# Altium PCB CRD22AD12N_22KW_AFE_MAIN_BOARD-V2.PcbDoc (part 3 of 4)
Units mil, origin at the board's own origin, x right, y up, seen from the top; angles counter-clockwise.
Board outline 14411 x 7330.3 mil, 4 copper layers (TOP, GND02, POWER03, BOTTOM), stack 78.531 mil thick; 589 components, 281 nets, 1401 pads, 282 vias.
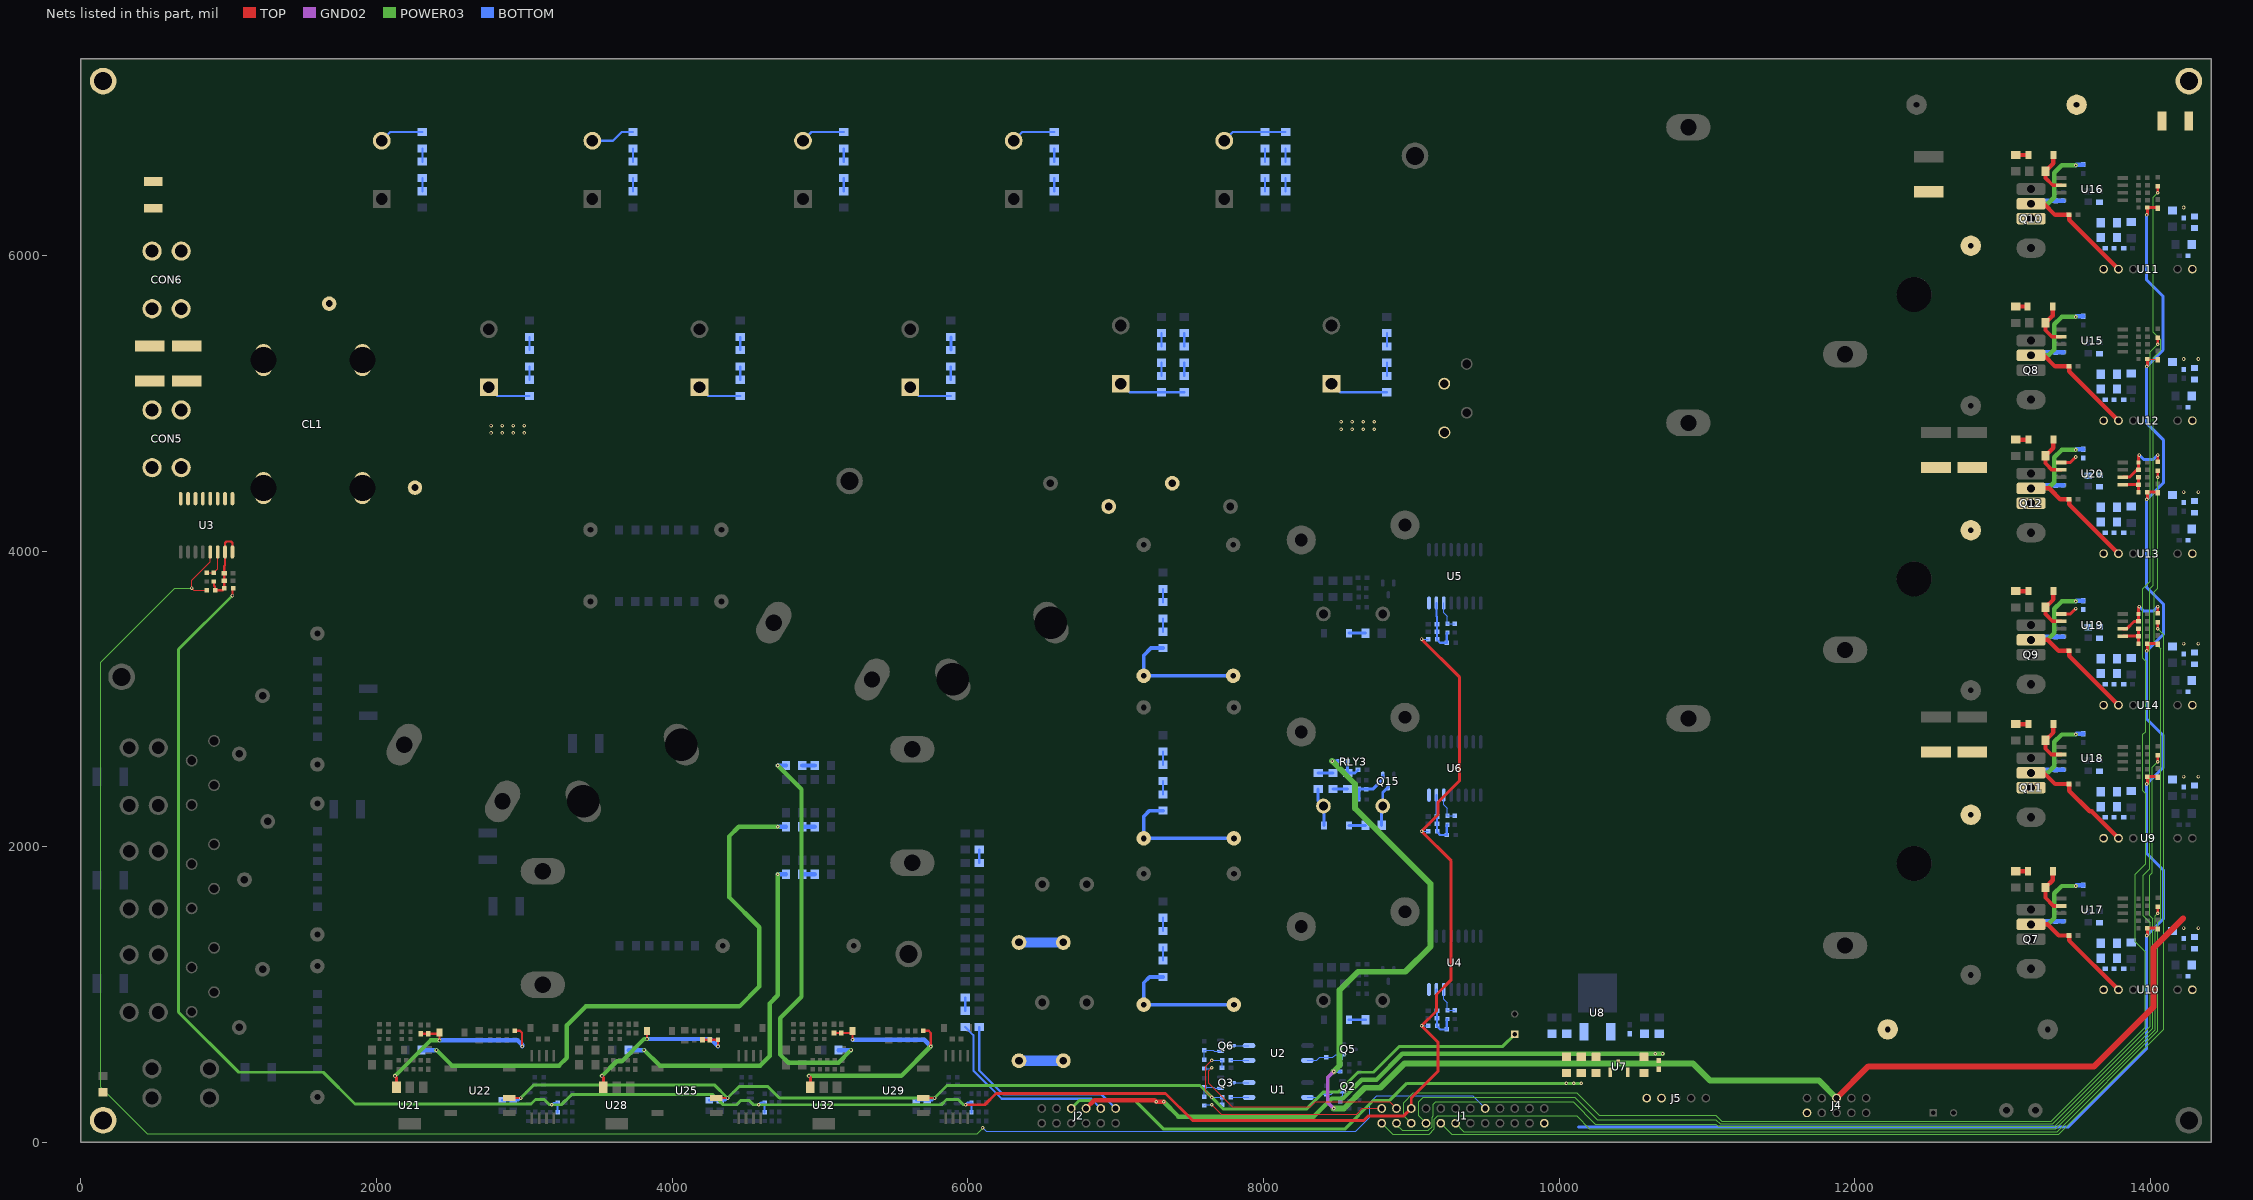
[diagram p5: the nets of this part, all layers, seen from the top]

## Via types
v1: diameter 24/24/24/24 (per signal layer), hole 12, TOP to BOTTOM, tented both sides, 282 vias

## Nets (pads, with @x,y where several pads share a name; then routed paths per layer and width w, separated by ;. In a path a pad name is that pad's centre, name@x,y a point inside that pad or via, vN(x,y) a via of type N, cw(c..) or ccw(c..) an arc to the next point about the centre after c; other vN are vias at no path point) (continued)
N17925295: C140.1 C141.1 R133.2 U19.1 | length 206.1
  TOP w20: U19.1@13814,3425 C141.1@13920.08,3425 ; R133.2@13920.08,3375 C141.1@13920.08,3425 ; C140.1@13920.08,3475 C141.1@13920.08,3425
N17925329: C142.1 R134.2 R136.1 U19.2 | length 423.8
  TOP w20: U19.2@13814,3475 13840,3475 13890,3525 C142.1@13920.08,3525 R136.1@13920.08,3575 13920.08,3620.08 v1(13925,3625) ; R134.2@14050,3579.92 v1(14050,3625)
  BOTTOM w20: v1(13925,3625) 13955,3595 14020,3595 v1(14050,3625)
N17925397: C143.1 C144.1 R135.1 U19.5 | length 114
  TOP w20: U19.5@13396.68,3575 13458.34,3575 v1(13495.34,3612)
N17925494: C147.1 C148.1 R137.2 U20.1 | length 206.1
  TOP w20: U20.1@13814,4450 C148.1@13920.08,4450 ; R137.2@13920.08,4400 C148.1@13920.08,4450 ; C147.1@13920.08,4500 C148.1@13920.08,4450
N17925544: C149.1 R138.2 R139.1 U20.2 | length 423.8
  TOP w20: U20.2@13814,4500 13816.5,4502.5 13861.3,4502.5 13903.29,4544.5 13914.58,4544.5 C149.1@13920.08,4550 R139.1@13920.08,4600 13920.08,4645.08 v1(13925,4650) ; R138.2@14050,4604.92 v1(14050,4650)
  BOTTOM w20: v1(13925,4650) 13955,4620 14020,4620 v1(14050,4650)
N17925612: C150.1 C151.1 R140.1 U20.5 | length 114
  TOP w20: U20.5@13396.68,4600 13458.34,4600 v1(13495.34,4637)
N17927817: C68.1 C69.1 R112.1 U10.1
N17928860: C86.1 C87.1 R114.1 U12.1
N17929090: C78.1 C79.1 R113.1 U11.1
N17930170: C104.1 C105.1 R116.1 U14.1
N17930400: C96.1 C97.1 R115.1 U13.1
N17951662: C39.1 C40.1 R98.2 R99.1 R100.1 U4.15 U4.16 | length 397.3
  BOTTOM w15: U4.15@9170,1034.76 9170,894.92 C40.1@9174.92,890 C39.1@9174.92,840 R98.2@9174.92,790 9174.92,785.08 9195,765 R100.1@9240.08,765 9240.08,830.16 R99.1@9245,835.08
N17951990: R99.2 R102.1 U4.14 | length 200.2
  BOTTOM w6: U4.14@9220,1034.76 9220,970 9245,945 R99.2@9245,894.92 R102.1@9295,894.92
N17952680: C41.1 C42.1 R103.2 R104.1 R105.1 U5.15 U5.16 | length 397.3
  BOTTOM w15: U5.15@9170,3649.76 9170,3560 9174.92,3555.08 C42.1@9174.92,3505 C41.1@9174.92,3455 R103.2@9174.92,3405 9174.92,3400.08 9195,3380 R105.1@9240.08,3380 9240.08,3445.16 R104.1@9245,3450.08
N17952780: R104.2 R109.1 U5.14 | length 200.2
  BOTTOM w6: U5.14@9220,3649.76 9220,3585 9245,3560 R104.2@9245,3509.92 R109.1@9295,3509.92
N17953229: C43.1 C44.1 R106.2 R107.1 R108.1 U6.15 U6.16 | length 397.3
  BOTTOM w15: U6.15@9170,2349.76 9170,2209.92 C44.1@9174.92,2205 C43.1@9174.92,2155 R106.2@9174.92,2105 9174.92,2100.08 9195,2080 R108.1@9240.08,2080 9240.08,2145.16 R107.1@9245,2150.08
N17953329: R107.2 R110.1 U6.14 | length 200.2
  BOTTOM w6: U6.14@9220,2349.76 9220,2285 9245,2260 R107.2@9245,2209.92 R110.1@9295,2209.92
N17988040: Q6.1 R67.1 R68.2 | length 178.5
  BOTTOM w6: R67.1@7600,559.92 R68.2@7600,625.08 7659.92,625.08 7667.4,617.6 Q6.1@7710.24,617.6
N17988101: Q6.3 U2.2 | length 112.4
  BOTTOM w6: Q6.3@7789.76,655 U2.2@7902.17,655
N17988123: Q5.1 R64.1 R66.2 U2.4 | length 321.9
  BOTTOM w6: U2.4@8297.83,555 8360,555 8380.08,575.08 R66.2@8425,575.08 8470.08,575.08 8487.6,592.6 Q5.1@8535.24,592.6 8535.24,565.24 8520.08,550.08 R64.1@8520.08,530
N17988189: R65.1 U2.1 | length 122.2
  BOTTOM w6: R65.1@7779.92,555 U2.1@7902.17,555
N17989219: Q3.1 R58.1 R59.2 | length 178.5
  BOTTOM w6: R58.1@7600,309.92 R59.2@7600,375.08 7662.52,375.08 7670,367.6 Q3.1@7710.24,367.6
N17989262: Q3.3 U1.2 | length 112.4
  BOTTOM w6: Q3.3@7789.76,405 U1.2@7902.17,405
N17989280: Q2.1 R51.1 R53.2 U1.4 | length 321.9
  BOTTOM w6: U1.4@8297.83,305 8365,305 8385.08,325.08 R53.2@8425,325.08 8460.08,325.08 8477.6,342.6 Q2.1@8535.24,342.6 8535.24,320.24 8520.08,305.08 R51.1@8520.08,280
N17989337: R52.1 U1.1 | length 122.2
  BOTTOM w6: R52.1@7779.92,305 U1.1@7902.17,305
N17992674: R73.1 R77.2 | length 89.8
  BOTTOM w15: R77.2@6077.76,1890.87 R73.1@6077.76,1980.63
N17992702: R92.1 R94.2 | length 89.8
  BOTTOM w15: R94.2@5982.76,890.87 R92.1@5982.76,980.63
N18031698: CL1.4 U3.1 U3.2 U3.3 U3.4
N18031715: C204.1 C205.1 CON5.1 CON5.2 CON5.3 CON5.4 U3.5 U3.6 U3.7 U3.8
N18031729: C37.1 C38.1 R95.2 R96.1 R97.1 U3.15 U3.16 | length 559.1
  TOP w15: R96.1@900,3795.08 900,3768 907.82,3760.18 907.82,3737.1 R97.1@909.92,3735 960.08,3735 970.08,3745 R95.2@970.08,3750 C37.1@970.08,3800 C38.1@970.08,3850 970,3850.08 970,3900 975,3905 U3.15@975,3994.76 975,4055 985,4065 1015,4065 1025,4055 U3.16@1025,3994.76
N18031813: R96.2 R101.1 U3.14 | length 200.2
  TOP w6: R101.1@850,3854.92 R96.2@900,3854.92 925,3879.92 U3.14@925,3994.76
N18060364: C204.2 C205.2 CL1.3 CON6.1 CON6.2 CON6.3 CON6.4 YC11.1
N18077527: C213.1 R191.2 R200.2 | length 158.2
  BOTTOM w20: R191.2@8569.92,2580 8569.92,2500.2 R200.2@8570,2500.12 8620.19,2500.12 C213.1@8640.08,2520
N18077715: C212.2 Q15.1 R198.1 R201.1 | length 289.8
  BOTTOM w20: R201.1@8640.08,2320 8645,2324.92 C212.2@8645,2390.08 R198.1@8695,2390.08 8740.08,2390.08 8807.6,2457.6 Q15.1@8807.6,2484.76
N18077724: Q15.3 R203.2 RLY3.2 | length 278.8
  BOTTOM w20: R203.2@8800.12,2145 8800.12,2243.5 8807.28,2250.66 RLY3.2@8807.28,2275.66 8807.28,2367.53 Q15.3@8845,2405.24
N18077784: D12.2 R199.1 RLY3.1 | length 261.6
  BOTTOM w20: R199.1@8370,2389.88 8370,2311.36 RLY3.1@8405.7,2275.66 8410.35,2271.02 D12.2@8410.35,2145
N18077797: R200.1 R202.2 | length 100
  BOTTOM w20: R202.2@8470,2389.88 R200.1@8570,2389.88
N18077799: R199.2 R202.1 | length 100
  BOTTOM w20: R199.2@8370,2500.12 R202.1@8470,2500.12
N18083752: R204.2 R206.1 | length 89.8
  BOTTOM w15: R206.1@7465,5185.12 R204.2@7465,5274.88
N18083755: R205.2 R207.1 | length 89.8
  BOTTOM w15: R207.1@8835,5185.12 R205.2@8835,5274.88
N18083758: R204.1 R208.2 | length 89.8
  BOTTOM w15: R204.1@7465,5385.12 R208.2@7465,5474.88
N18083761: R205.1 R209.2 | length 89.8
  BOTTOM w15: R205.1@8835,5385.12 R209.2@8835,5474.88
N18084124: R210.1 R212.2 | length 89.8
  BOTTOM w15: R210.1@8150,6435.12 R212.2@8150,6524.88
N18084127: R211.1 R213.2 | length 89.8
  BOTTOM w15: R211.1@2310,6435.12 R213.2@2310,6524.88
N18084130: R213.1 R215.2 | length 89.8
  BOTTOM w15: R213.1@2310,6635.12 R215.2@2310,6724.88
N18084133: R212.1 R214.2 | length 89.8
  BOTTOM w15: R212.1@8150,6635.12 R214.2@8150,6724.88
N18084369: R216.2 R218.1 | length 89.8
  BOTTOM w15: R218.1@3035,5160.12 R216.2@3035,5249.88
N18084371: R217.2 R220.1 | length 89.8
  BOTTOM w15: R220.1@4460,5160.12 R217.2@4460,5249.88
N18084373: R216.1 R219.2 | length 89.8
  BOTTOM w15: R216.1@3035,5360.12 R219.2@3035,5449.88
N18084375: R217.1 R221.2 | length 89.8
  BOTTOM w15: R217.1@4460,5360.12 R221.2@4460,5449.88
N18084659: R222.1 R225.2 | length 89.8
  BOTTOM w15: R222.1@3735,6435.12 R225.2@3735,6524.88
N18084661: R223.1 R224.2 | length 89.8
  BOTTOM w15: R223.1@6585,6435.12 R224.2@6585,6524.88
N18084679: R224.1 R227.2 | length 89.8
  BOTTOM w15: R224.1@6585,6635.12 R227.2@6585,6724.88
N18084681: R225.1 R226.2 | length 89.8
  BOTTOM w15: R225.1@3735,6635.12 R226.2@3735,6724.88
N18089484: R228.2 R229.1 | length 89.8
  BOTTOM w15: R229.1@7310,5185.12 R228.2@7310,5274.88
N18089486: R228.1 R230.2 | length 89.8
  BOTTOM w15: R228.1@7310,5385.12 R230.2@7310,5474.88
N18089654: R231.2 R232.1 | length 89.8
  BOTTOM w15: R232.1@5885,5160.12 R231.2@5885,5249.88
N18089656: R231.1 R233.2 | length 89.8
  BOTTOM w20: R231.1@5885,5360.12 R233.2@5885,5449.88
N18089831: R234.1 R235.2 | length 89.8
  BOTTOM w15: R234.1@8010,6435.12 R235.2@8010,6524.88
N18089841: R235.1 R236.2 | length 89.8
  BOTTOM w15: R235.1@8010,6635.12 R236.2@8010,6724.88
N18090018: R237.1 R238.2 | length 89.8
  BOTTOM w15: R237.1@5160,6435.12 R238.2@5160,6524.88
N18090028: R238.1 R239.2 | length 89.8
  BOTTOM w15: R238.1@5160,6635.12 R239.2@5160,6724.88
N18151288: R241.1 R244.2 | length 2333
  POWER03 w30: v1(3810,625) 3915,520 4595,520 4660,585 4660,940 4715,995 v1(4715,1815)
  BOTTOM w30: R241.1@3705.12,625 v1(3810,625) ; v1(4715,1815) R244.2@4769.88,1815
N18151343: R240.1 R243.2 | length 4190.6
  POWER03 w30: v1(2405,625) 2510,520 3235,520 3288,573 3288,793 3415,920 4455,920 4590,1055 4590,1455 4385,1660 4385,2070 4450,2135 v1(4715,2135)
  BOTTOM w30: R240.1@2305.12,625 v1(2405,625) ; v1(4715,2135) R243.2@4769.88,2135
N18151366: R242.1 R245.2 | length 2759.1
  POWER03 w30: v1(4715,2550) 4875,2390 4875,985 4730,840 4730,595 4785,540 5125,540 v1(5210,625)
  BOTTOM w30: v1(4715,2550) R245.2@4769.88,2550 ; R242.1@5125.12,625 v1(5210,625)
N18156742: R9.1 R18.1 R27.1 XC3.2 XC6.2 XC9.2 XC10.2 XC11.2 XC12.2 | length 2702.4
  BOTTOM w25: R27.1@7320,1119.88 7229.88,1119.88 7190,1080 XC9.2@7190,932.09 XC10.2@7800,932.09 ; R9.1@7320,2244.88 7229.88,2244.88 7190,2205 XC3.2@7190,2057.09 XC12.2@7800,2057.09 ; R18.1@7320,3344.88 7239.88,3344.88 7190,3295 XC6.2@7190,3157.09 XC11.2@7795,3157.09
N18156744: R12.1 R15.2 | length 89.8
  BOTTOM w15: R15.2@7320,3655.12 R12.1@7320,3744.88
N18156746: R15.1 R18.2 | length 89.8
  BOTTOM w15: R18.2@7320,3455.12 R15.1@7320,3544.88
N18156778: R3.1 R6.2 | length 89.8
  BOTTOM w15: R6.2@7320,2555.12 R3.1@7320,2644.88
N18156780: R6.1 R9.2 | length 89.8
  BOTTOM w15: R9.2@7320,2355.12 R6.1@7320,2444.88
N18156832: R21.1 R24.2 | length 89.8
  BOTTOM w15: R24.2@7320,1430.12 R21.1@7320,1519.88
N18156834: R24.1 R27.2 | length 89.8
  BOTTOM w15: R27.2@7320,1230.12 R24.1@7320,1319.89
N18158495: MT3.1 YC11.2
N18179724: D13.1 R258.2 | length 81.1
  TOP w30: R258.2@13090,1835.12 13090.12,1835 D13.1@13171.03,1835
N18179852: D14.1 R259.2 | length 85.4
  TOP w30: R259.2@13090,2830.12 13175.23,2830.12 D14.1@13175.35,2830
N18179938: D15.1 R260.2 | length 85.4
  TOP w30: R260.2@13090,6680.12 13175.23,6680.12 D15.1@13175.35,6680
N18180027: D16.1 R261.2 | length 80.4
  TOP w30: R261.2@13090,5655.12 13170.23,5655.12 D16.1@13170.35,5655
N18180134: D17.1 R262.2 | length 85.4
  TOP w30: R262.2@13090,3730.12 13175.23,3730.12 D17.1@13175.35,3730
N18180239: D18.1 R263.2 | length 85.4
  TOP w30: R263.2@13090,4755.12 13175.23,4755.12 D18.1@13175.35,4755
N18184240: R243.1 R264.2 | length 84.8
  BOTTOM w30: R243.1@4880.12,2135 R264.2@4964.88,2135
N18184278: R244.1 R265.2 | length 84.8
  BOTTOM w30: R244.1@4880.12,1815 R265.2@4964.88,1815
N18184299: R245.1 R266.2 | length 84.8
  BOTTOM w30: R245.1@4880.12,2550 R266.2@4964.88,2550
N18189276: MT2.1 YC10.2
N18202622: MT1.1 R267.2
N179111791: RV1.1 RV2.2 | length 300
  BOTTOM w70: RV1.1@6346.26,1353.15 RV2.2@6646.26,1353.15
N179111870: D1.1 R42.1 | length 110.2
  BOTTOM w20: D1.1@8579.65,830 R42.1@8689.88,830
N179113761: RV3.1 RV4.2
N179113920: D2.1 R60.1 | length 110.2
  BOTTOM w20: D2.1@8579.65,3445 R60.1@8689.88,3445
N180778471: RV5.2 RV6.1 | length 300
  BOTTOM w70: RV6.1@6346.26,553.15 RV5.2@6646.26,553.15
N180778550: D12.1 R203.1 | length 110.2
  BOTTOM w20: D12.1@8579.65,2145 R203.1@8689.88,2145
OUTPUT_OC: J1.16 R97.2 U3.13 | length 13818.6
  TOP w6: R97.2@850.08,3735 765,3735 v1(750,3750) 750,3805 875,3930 U3.13@875,3994.76
  POWER03 w6: v1(750,3750) 634.72,3750 135,3250.28 135,375 450,60 6065,60 6100,95 v1(6100,100)
  BOTTOM w6: v1(6100,100) 6125,75 8625,75 8720,170 8720,270 8765,315 9415,315 J1.16@9500,230
P6.5V: C47.2 C48.2 C52.2 J4.10 U8.3
PFC_G_HA: C7.2 C59.2 C60.2 C61.2 C71.1 C72.1 C130.2 C131.1 Q7.3 R74.1 U10.6 | length 1579.1
  TOP w30: Q7.3@13192.96,1475 13305.68,1475 13380.68,1400 C131.1@13450.42,1400 13450.42,1366.9 U10.6@13784.25,1033.07
  POWER03 w30: Q7.3@13192.96,1475 13306.68,1475 13350.68,1519 13350.68,1685 13400.68,1735 v1(13495.34,1735)
  BOTTOM w30: Q7.3@13192.96,1475 13205.68,1475 13225.76,1495.08 C7.2@13360.68,1495.08 R74.1@13410.68,1495.08 ; v1(13495.34,1735) 13500.26,1739.92 C130.2@13545.34,1739.92
PFC_G_HB: C8.2 C77.2 C80.2 C81.2 C88.1 C90.1 C116.2 C117.1 Q8.3 R75.1 U12.6 | length 1582
  TOP w30: Q8.3@13192.96,5325 13245.68,5325 13280.76,5325 13355.76,5250 C117.1@13450.42,5250 13450.42,5216.9 U12.6@13784.25,4883.07
  POWER03 w30: Q8.3@13192.96,5325 13311.68,5325 13350.68,5364 13350.68,5535 13400.68,5585 v1(13495.34,5585)
  BOTTOM w30: Q8.3@13192.96,5325 13213.04,5345.08 13225.76,5345.08 13320.68,5345.08 C8.2@13360.68,5345.08 R75.1@13410.68,5345.08 ; v1(13495.34,5585) 13500.26,5589.92 C116.2@13545.34,5589.92
PFC_G_HC: C9.2 C95.2 C98.2 C99.2 C106.1 C108.1 C144.2 C145.1 Q9.3 R76.1 U14.6 | length 1577.4
  TOP w30: Q9.3@13192.96,3400 13305,3400 13355,3350 13380,3325 C145.1@13450.42,3325 13450.42,3291.9 U14.6@13784.25,2958.07
  POWER03 w30: Q9.3@13192.96,3400 13303.68,3400 13350.68,3447 13350.68,3610 13400.68,3660 v1(13495.34,3660)
  BOTTOM w30: Q9.3@13192.96,3400 13213.04,3420.08 C9.2@13360.68,3420.08 R76.1@13410.68,3420.08 ; v1(13495.34,3660) 13500.26,3664.92 C144.2@13545.34,3664.92
PFC_G_LA: C36.2 C56.2 C57.2 C58.2 C70.1 C73.1 C137.2 C138.1 Q11.3 R91.1 U9.6 | length 1585.7
  TOP w30: Q11.3@13192.96,2500 13280.76,2500 13355.76,2425 C138.1@13450.42,2425 13450.42,2379.58 13590.31,2239.68 13602.63,2239.68 U9.6@13784.25,2058.07
  POWER03 w30: Q11.3@13192.96,2500 13305.68,2500 13350.68,2545 13350.68,2710 13400.68,2760 v1(13495.34,2760)
  BOTTOM w30: Q11.3@13192.96,2500 13213.04,2520.08 C36.2@13360.68,2520.08 R91.1@13410.68,2520.08 ; v1(13495.34,2760) 13500.26,2764.92 C137.2@13545.34,2764.92
PFC_G_LB: C34.2 C74.2 C75.2 C76.2 C89.1 C91.1 C123.2 C124.1 Q10.3 R87.1 U11.6 | length 1579.1
  TOP w30: Q10.3@13192.96,6350 13280.76,6350 13355.76,6275 C124.1@13450.42,6275 13450.42,6241.9 U11.6@13784.25,5908.07
  POWER03 w30: Q10.3@13192.96,6350 13306.68,6350 13350.68,6394 13350.68,6560 13400.68,6610 v1(13495.34,6610)
  BOTTOM w30: Q10.3@13192.96,6350 13205.68,6350 13225.76,6370.08 C34.2@13360.68,6370.08 R87.1@13410.68,6370.08 ; v1(13495.34,6610) 13500.26,6614.92 C123.2@13545.34,6614.92
PFC_G_LC: C35.2 C92.2 C93.2 C94.2 C107.1 C109.1 C151.2 C152.1 Q12.3 R88.1 U13.6 | length 1580.3
  TOP w30: Q12.3@13192.96,4425 13315.68,4425 13325.74,4414.94 13390.68,4350 C152.1@13450.42,4350 13450.42,4316.9 U13.6@13784.25,3983.07
  POWER03 w30: Q12.3@13192.96,4425 13308.68,4425 13350.68,4467 13350.68,4635 13400.68,4685 v1(13495.34,4685)
  BOTTOM w30: Q12.3@13192.96,4425 13213.04,4445.08 C35.2@13360.68,4445.08 R88.1@13410.68,4445.08 ; v1(13495.34,4685) 13500.26,4689.92 C151.2@13545.34,4689.92
PFCDRVHA: D13.2 R69.1 U17.6 | length 329.2
  TOP w25: R69.1@13290.8,1725 13290.8,1654.88 13345.68,1600 U17.6@13396.68,1600
  TOP w30: R69.1@13290.8,1725 13340.33,1774.53 D13.2@13340.33,1835
PFCDRVHB: D16.2 R70.1 U15.6 | length 305.2
  TOP w25: R70.1@13290.8,5545 13290.8,5494.2 13335,5450 U15.6@13396.68,5450
  TOP w30: R70.1@13290.8,5545 13339.65,5593.85 D16.2@13339.65,5655
PFCDRVHC: D17.2 R71.1 U19.6 | length 304.4
  TOP w25: R71.1@13290.8,3620 13290.8,3574.2 13340,3525 U19.6@13396.68,3525
  TOP w30: R71.1@13290.8,3620 13344.65,3673.85 D17.2@13344.65,3730
PFCDRVLA: D14.2 R86.1 U18.6 | length 310.2
  TOP w25: R86.1@13290.8,2720 13290.8,2664.2 13330,2625 U18.6@13396.68,2625
  TOP w30: R86.1@13290.8,2720 13344.65,2773.85 D14.2@13344.65,2830
PFCDRVLB: D15.2 R82.1 U16.6 | length 304.4
  TOP w25: R82.1@13290.8,6570 13290.8,6524.2 13340,6475 U16.6@13396.68,6475
  TOP w30: R82.1@13290.8,6570 13344.65,6623.85 D15.2@13344.65,6680
PFCDRVLC: D18.2 R85.1 U20.6 | length 307.3
  TOP w25: R85.1@13290.8,4645 13290.8,4594.2 13335,4550 U20.6@13396.68,4550
  TOP w30: R85.1@13290.8,4645 13344.65,4698.85 D18.2@13344.65,4755
PGND: C19.2 C20.2 C21.2 C23.2 C24.2 C27.2 C28.2 C31.2 C32.2 C33.2 C45.1 C46.1 C49.1 C50.1 C51.1 C206.2 C207.2 C208.2 C209.2 C210.2 CL1.2 J2.5 J5.5 Q10.2 Q11.2 Q12.2 R214.1 R215.1 R226.1 R227.1 R236.1 R239.1 TP2.1 U7.2 YC10.1 | length 5780.1
  TOP w30: J2.5@6800,230 6855,285 7265,285 v1(7275,275) v1(7325,275)
  POWER03 w30: v1(7325,275) 7425,175 8340,175 8462.5,297.5 8537.5,297.5 8665,425 8765,425 8940,600 v1(10650,600) v1(10700,600)
  BOTTOM w15: C27.2@2035,6776.85 2093.27,6835.12 R215.1@2310,6835.12 ; C28.2@3460,6776.85 3600,6776.85 3658.27,6835.12 R226.1@3735,6835.12 ; C23.2@4885,6776.85 4943.27,6835.12 R239.1@5160,6835.12 ; C24.2@6310,6776.85 6368.27,6835.12 R227.1@6585,6835.12 ; C31.2@7735,6776.85 7793.27,6835.12 R236.1@8010,6835.12 R214.1@8150,6835.12
PWM1A: J1.1 R126.1 | length 6507.3
  TOP w20: v1(14050,1550) R126.1@14050,1595.08
  POWER03 w6: J1.1@8800,130 8874.5,55.5 9120.5,55.5 9156,91 9156,157 9178,179 10118,179 10205.61,91.39 13361.39,91.39 14034,764 14034,1534 v1(14050,1550)
PWM1B: J1.3 R130.1 | length 7529.9
  TOP w20: v1(14050,2575) R130.1@14050,2620.08
  POWER03 w6: J1.3@8900,130 8900,119 8938,81 9116,81 9142,107 9142,172 9149,179 9149,259 9165,275 10095.15,275 10246.15,124 11061,124 11075.93,109.07 13354.07,109.07 14016,771 14016,1513 13997,1532 13997,1808 14012,1823 14012,2537 v1(14050,2575)
PWM1C: J1.5 R118.1 | length 10332.5
  TOP w20: v1(14050,5400) R118.1@14050,5445.08
  POWER03 w6: J1.5@9000,130 8950,180 8950,270 9015,335 10120,335 10271,184 11061,184 11100,145 13330,145 13966.01,781.01 13966.01,1288.99 13897,1358 13897,1813 13969,1885 13969,2360 13950,2379 13950,2762 13968,2780 13968,3257 13950,3275 13950,3745 14000,3795 14000,5350 v1(14050,5400)
PWM1D: J1.7 R122.1 | length 11263.8
  TOP w20: v1(14050,6425) R122.1@14050,6470.08
  POWER03 w6: J1.7@9100,130 9050,180 9050,275 9080,305 10107.57,305 10258.57,154 11061,154 11089.93,125.07 13340.07,125.07 14000,785 14000,1487 13952,1535 13952,1808 13996,1852 13996,3745 14020,3769 14020,5310 14070,5360 14070,5430 14019,5481 14019,6394 v1(14050,6425)
PWM1E: J1.9 R134.1 | length 7986.4
  TOP w20: v1(14050,3475) R134.1@14050,3520.08
  POWER03 w6: J1.9@9200,130 9274.5,55.5 13380.5,55.5 14090,765 14090,3435 v1(14050,3475)
PWM1F: J1.11 R138.1 | length 8882.9
  TOP w20: v1(14050,4500) R138.1@14050,4545.08
  POWER03 w6: J1.11@9300,130 9356.29,73.71 13368.71,73.71 14050,755 14050,1490 14070,1510 14070,3340 14025,3385 14025,3725 14050,3750 v1(14050,4500)
RLYCTRL1: J1.2 R58.2 | length 1245.5
  TOP w6: v1(7650,255) 7715,190 8630,190 8670,230 J1.2@8800,230
  BOTTOM w6: R58.2@7600,250.08 7604.92,255 v1(7650,255)
RLYCTRL2: J1.4 R67.2 | length 1535.2
  TOP w6: v1(7650,505) 7629.5,484.5 7629.5,421.51 7630,421.01 7630,400 7790,240 8315,240 8350,275 8855,275 J1.4@8900,230
  BOTTOM w6: R67.2@7600,500.08 7645.08,500.08 v1(7650,505)
VA+5V: C159.2 C160.2 D3.2 R142.1 U21.3 | length 1392.4
  TOP w15: C159.2@2299.99,735.08 C160.2@2350,735.08 2415.43,735.08 D3.2@2425.35,745 v1(2425.35,690) ; R142.1@2935,754.92 2970.08,754.92 2985,740 v1(2985,650)
  TOP w20: v1(2125,450) 2134.45,440.55 U21.3@2134.45,374.02
  POWER03 w30: v1(2125,450) 2365,690 v1(2425.35,690)
  BOTTOM w30: v1(2425.35,690) 2955,690 2985,660 v1(2985,650)
VB+5V: C181.2 C182.2 D6.2 R158.1 U28.3 | length 1194.2
  TOP w15: v1(3830.35,700) D6.2@3830.35,755 ; C182.2@4205,695.08 C181.2@4254.99,695.08 R158.1@4310,695.08 v1(4310,650)
  TOP w20: v1(3525,450) 3534.45,440.55 U28.3@3534.45,374.02
  POWER03 w30: v1(3525,450) 3625,550 3660,550 3810,700 v1(3830.35,700)
  BOTTOM w30: v1(3830.35,700) 4260,700 v1(4310,650)
VC+5V: C198.2 C199.2 D8.2 R171.1 U32.3 | length 1873.7
  TOP w15: C198.2@5094.99,740.08 C199.2@5145,740.08 5205.43,740.08 D8.2@5220.35,755 v1(5220.35,695) ; R171.1@5700,754.92 5735.08,754.92 5750,740 v1(5750,650)
  TOP w20: v1(4925,450) 4934.45,440.55 U32.3@4934.45,374.02
  POWER03 w30: v1(4925,450) 5550,450 v1(5750,650)
  BOTTOM w30: v1(5220.35,695) 5705,695 v1(5750,650)
VO1+: J2.1 R93.1 | length 1322.2
  BOTTOM w15: R93.1@6077.76,780.63 6077.76,487.24 6240,325 6905,325 J2.1@7000,230
VO2+: J2.3 R94.1 | length 1285
  BOTTOM w15: R94.1@5982.76,780.63 6037.76,725.63 6037.76,487.24 6230,295 6835,295 J2.3@6900,230
VP3.3D: J1.6 R95.1 R98.1 R103.1 R106.1 R141.1 R143.1 R157.1 R159.1 R172.1 R174.1 | length 16037.4
  TOP w15: v1(1025,3700) 1025,3745.08 R95.1@1029.92,3750
  TOP w20: v1(5985,255) 6114,255 6191,332 7338,332 7520,150 8680,150 8710,180 8950,180 J1.6@9000,230 9000,300 9180,480 9180,680 v1(9070,790) 9170,890 9170,1000 9270,1100 9270,1905 v1(9070,2105) 9180,2215 9180,2300 9325,2445 9325,3150 v1(9070,3405)
  POWER03 w20: v1(1025,3700) 661,3336 661,881.56 1067.56,475 1640,475 1855,260 3045.01,260 3075.01,290 3135,290 3170,255 v1(3185,255) 3250,255 3320,325 4275,325 4345,255 4435,255 4465,285 4520,285 4550,255 v1(4585,255) 5820,255 5855,290 5935,290 5970,255 v1(5985,255)
  BOTTOM w6: v1(9070,790) R98.1@9115.08,790 ; v1(9070,2105) R106.1@9115.08,2105 ; v1(9070,3405) R103.1@9115.08,3405
  BOTTOM w15: v1(3185,255) 3185.82,255 3196.82,266 3220.92,266 R141.1@3225,270.08 R143.1@3225,204.92 ; v1(4585,255) 4593.06,263.06 cw(c4610,246.13) 4610,270.08 R157.1@4625,270.08 R159.1@4625,204.92 ; v1(5985,255) 5998,268 6022.92,268 R172.1@6025,270.08 R174.1@6025,204.92
VP+5V: C3.1 C6.1 C53.2 C54.2 C55.1 C111.1 C118.1 C125.1 C132.1 C139.1 C146.1 C155.2 C156.2 C169.2 C170.2 C183.2 C184.2 J1.23 R52.2 R65.2 R117.1 R121.1 R125.1 R129.1 R133.1 R137.1 U8.1 U22.2 U25.2 U29.2 | length 19240.9
  TOP w6: v1(7650,305) 7610,345 7610,515 v1(7650,555) ; R117.1@13979.92,5300 14045.08,5300 C111.1@14050,5295.08
  TOP w15: U22.2@2898.5,300 v1(2975,300) ; U25.2@4298.5,300 v1(4375,300) ; U29.2@5698.5,300 v1(5775,300)
  TOP w20: v1(13975,1400) 13979.92,1404.92 R125.1@13979.92,1450 14045.08,1450 C125.1@14050,1445.08 ; v1(13975,2425) 13979.92,2429.92 R129.1@13979.92,2475 14045.08,2475 C132.1@14050,2470.08 ; v1(13975,3325) 13979.92,3329.92 R133.1@13979.92,3375 14045.08,3375 C139.1@14050,3370.08 ; v1(13975,4350) 13979.92,4354.92 R137.1@13979.92,4400 14000,4400 14045.08,4400 C146.1@14050,4395.08 ; v1(13975,5250) 13979.92,5254.92 R117.1@13979.92,5300 ; v1(13975,6275) 13979.92,6279.92 R121.1@13979.92,6325 14045.08,6325 C118.1@14050,6320.08
  POWER03 w20: v1(2975,300) 3065,390 4285,390 v1(4375,300) 4455,380 4645,380 4725,300 v1(5775,300) 5860,385 7570,385 v1(7650,305) 7730,225 8290,225 8407.49,342.49 8507.49,342.49 8640,475 8745,475 8920,650 9618.9,650 C55.1@9700,731.1
  BOTTOM w6: v1(7650,305) R52.2@7720.08,305 C3.1@7720.08,255 ; v1(7650,555) R65.2@7720.08,555 C6.1@7720.08,505
  BOTTOM w15: C155.2@2850,285.04 C156.2@2925,285.04 2960.04,285.04 v1(2975,300) ; C170.2@4250,285.04 C169.2@4325,285.04 4360.04,285.04 v1(4375,300) ; C184.2@5650,285.04 C183.2@5725,285.04 5760.04,285.04 v1(5775,300)
  BOTTOM w20: 10130,105 13445,105 13975,635 v1(13975,1400) 14090,1515 14090,1840 13975,1955 v1(13975,2425) 14085,2535 14085,2755 13975,2865 v1(13975,3325) 14090,3440 14090,3469.32 14090,3640 13975,3755 v1(13975,4350) 14090,4465 14090,4750 13975,4865 v1(13975,5250) 14085,5360 14085,5725 13975,5835 v1(13975,6275)
VP+15V: C62.1 C63.1 C66.1 C67.1 C82.1 C83.1 C84.1 C85.1 C100.1 C101.1 C102.1 C103.1 J4.5 R36.1 R57.1 R111.2 R112.2 R113.2 R114.2 R115.2 R116.2 R191.1 | length 9961.9
  TOP w40: J4.5@11877.21,300 12092.21,515 13620,515 14020,915 14020,1314 14222.84,1516.84
  GND02 w25: v1(8475,230) 8435,270 8435,440 v1(8475,480)
  POWER03 w40: v1(8465,2580) 8620,2425 8620,2260 9130,1750 9130,1325 8960,1155 8640,1155 8515,1030 8515,520 v1(8475,480) ; v1(8475,230) 8545,230 8685,370 8790,370 8955,535 10905,535 11020,420 11757.21,420 J4.5@11877.21,300
  BOTTOM w20: v1(8465,2580) R191.1@8510.08,2580 ; v1(8475,230) R36.1@8520.08,230 ; v1(8475,480) R57.1@8520.08,480
  other v1: 14225,1450 14325,1450 14225,2475 14325,2475 14225,3375 14325,3375 14225,4400 14325,4400 14225,5300 14325,5300 14225,6325
VP+15V_PFCHA: C59.1 C60.1 C61.1 R128.2 U10.7
VP+15V_PFCHB: C77.1 C80.1 C81.1 R120.2 U12.7
VP+15V_PFCHC: C95.1 C98.1 C99.1 R135.2 U14.7
VP+15V_PFCLA: C56.1 C57.1 C58.1 R132.2 U9.7
VP+15V_PFCLB: C74.1 C75.1 C76.1 R124.2 U11.7
VP+15V_PFCLC: C92.1 C93.1 C94.1 R140.2 U13.7
VPFC: C10.1 C11.1 C13.1 C16.1 C17.1 CL1.1 F7.2 F8.2 R206.2 R207.2 R218.2 R220.2 R229.2 R232.2 TP1.1 | length 1750.7
  BOTTOM w15: C17.1@2760,5108.15 2818.27,5049.88 R218.2@3035,5049.88 ; C10.1@4185,5108.15 4243.27,5049.88 R220.2@4460,5049.88 ; C11.1@5610,5108.15 5668.27,5049.88 R232.2@5885,5049.88 ; C13.1@7035,5133.15 7093.27,5074.88 R229.2@7310,5074.88 R206.2@7465,5074.88 ; C16.1@8460,5133.15 8518.27,5074.88 R207.2@8835,5074.88
  other v1: 2775,4800 2850,4800 2925,4800 3000,4800 8525,4825 8600,4825 8675,4825 8750,4825 2775,4850 2850,4850 2925,4850 3000,4850 8525,4875 8600,4875 8675,4875 8750,4875
VS+5V: C49.2 C50.2 C51.2 J2.7 U7.1 | length 3682
  POWER03 w20: J2.7@6700,230 6755,285 7130,285 7325,90 8550,90 8745,285 8855,285 8970,400 v1(10050,400) v1(10100,400) v1(10150,400)
VS+15V: C45.2 C46.2 J5.4 U7.3
pads on no net: J2.8 J2.9 J2.10 J4.3 J4.4 J4.7 J4.8 J5.3 MTH122.1 NTH236.1 U22.5 U25.5 U29.5

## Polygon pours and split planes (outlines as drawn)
VPFC on GND02 "GND02-VPFC" (solid, pour order 99): 2245,5975 9171.72,5975 9305,5841.72 9305,4785 9265,4745 6591.72,4745 6146.72,4300 3591.64,4300 1850,4300 1800,4350 1800,4690 2090,4980 2090,5605 2090,5820
N179113761 on GND02 "GND02-N179113761" (solid, pour order 38): 7465,4255 6900,4255 6845,4310 6845,4615 6895,4665 7470,4665 7532.5,4602.5 7532.5,4322.5 7465,4255
AC_LC on GND02 "GND02-AC_LC" (solid, pour order 53): 5980,1230 5980,2100 5505,2575 5505,2685 5555,2735 5775,2735 6185,2325 6185,1375 6535,1025 6560,1000 6560,850 6535,825 6385,825 5980,1230
AC_LB1 on GND02 "GND02-AC_LB1" (solid, pour order 59): 7685,4625 7725,4665 9020,4665 9080,4605 9080,4110 9030,4060 8630,4060 8435,4255 7740,4255 7685,4310 7685,4625
N18060364 on GND02 "GND02-N18060364" (solid, pour order 64): 355,6335 355,5360 365,5350 955,5350 1125,5180 1300,5180 1340,5220 1340,6300 1295,6345 365,6345 355,6335
AC_LB on GND02 "GND02-AC_LB" (solid, pour order 70): 17 vertices, not listed, extent 5810,2865 8366.25,4177.5
GGND on GND02 "GND02-GGND" (solid, pour order 74): 95 vertices, not listed, extent 14110,1020 14361,6430
N17908016 on GND02 "GND02-N17908016" (solid, pour order 78): 2970,1545 2970,1930 3025,1985 5685,1985 5745,1925 5750,1925 5750,1625 5320,1195 4685,1195 4445,1435 3925,1435 3080,1435 2970,1545
N17908062 on GND02 "GND02-N17908062" (solid, pour order 79): 69 vertices, not listed, extent 2620,2145 4780,3705
N18156742 on GND02 "GND02-N18156742" (solid, pour order 83): 7070,885 7035,920 7035,3070 7175,3210 7855,3210 7890,3175 7915,3150 7915,950 7890,925 7850,885 7070,885
N17908018 on GND02 "GND02-N17908018" (solid, pour order 90): 28 vertices, not listed, extent 3096,2145 6670,4225
GND_EARTH on GND02 "GND02-No Net 1" (solid, pour order 96): 84 vertices, not listed, extent 50,50 3645,3305
AGND on GND02 "GND02-No Net" (solid, pour order 97): 1649 vertices, not listed, extent 2745,50 14361,6755
PGND on GND02 "GND02-PGND" (solid, pour order 102): 285 vertices, not listed, extent 1565,640 14361,7280.3
GND_EARTH on GND02 "NONET_L-01_P-001" (solid, pour order 105): 20 vertices, not listed, extent 50,50 3645,3305
AGND on GND02 "NONET_L-01_P-001" (solid, pour order 106): 88 vertices, not listed, extent 2745,50 14361,6755
N17908016 on TOP "TOP-N17908016" (solid, pour order 86): 50 vertices, not listed, extent 2980,976 5930,1974.36
N17896613 on TOP "TOP-N17896613" (solid, pour order 81): 152 vertices, not listed, extent 857.5,255 3275,1860
N17898200 on TOP "TOP-N17898200" (solid, pour order 72): 103 vertices, not listed, extent 840,1925 2320,3000
VP+15V on TOP "NONET_L-01_P-001" (solid, pour order 104): 14205,1335 14195,1345 14195,6325 14210,6340 14330,6340 14351,6319 14351,1351 14335,1335
AGND on TOP "TOP-AGND 3" (solid, pour order 2): 25 vertices, not listed, extent 13785,2508 14065,2783
AGND on TOP "TOP-AGND 4" (solid, pour order 3): 25 vertices, not listed, extent 13785,3408 14065,3683
AGND on TOP "TOP-AGND 5" (solid, pour order 4): 25 vertices, not listed, extent 13785,4433 14065,4708
AGND on TOP "TOP-AGND" (solid, pour order 5): 25 vertices, not listed, extent 13785,5333 14065,5608
AGND on TOP "TOP-AGND 2" (solid, pour order 6): 25 vertices, not listed, extent 13785,1483 14065,1758
AGND on TOP "TOP-AGND 1" (solid, pour order 7): 25 vertices, not listed, extent 13785,6358 14065,6633
AC_LBC_G on TOP "TOP-AC_LBC_G" (solid, pour order 8): 4260,515 4260,610 4275,625 4505,625 4510,620 4510,560 4510,525 4510,505 4480,475 4265,475 4260,480 4260,515
AC_LCA_G on TOP "TOP-AC_LCA_G" (solid, pour order 9): 5660,515 5660,610 5675,625 5905,625 5910,620 5910,560 5910,525 5910,505 5880,475 5665,475 5660,480 5660,515
AC_LAB_G on TOP "TOP-AC_LAB_G" (solid, pour order 10): 2860,515 2860,610 2875,625 3105,625 3110,620 3110,560 3110,525 3110,505 3080,475 2865,475 2860,480 2860,515
VS+5V on TOP "TOP-VS+5V" (solid, pour order 11): 10350,505 10305,505 10295,495 10025,495 10005,475 10005,395 10015,385 10340,385 10360,405 10360,495 10350,505
N18189276 on TOP "TOP-N18189276" (solid, pour order 12): 14150,7105 14150,7235 14180,7265 14325,7265 14350,7240 14350,6865 14335,6850 14245,6850 14235,6860 14235,7020 14150,7105
VS+15V on TOP "TOP-VS+15V" (solid, pour order 14): 10465,250 10455,260 10455,500 10460,505 10505,505 10515,495 10620,495 10635,510 10695,510 10725,480 10725,260 10715,250 10465,250
N18202622 on TOP "TOP-N18202622" (solid, pour order 18): 55,50 50,55 50,350 65,365 260,365 280,345 280,70 260,50 55,50
N17916039 on TOP "TOP-N17916039 3" (solid, pour order 19): 12350,7095 12525,7095 12565,7095 12595,7065 12595,7025 12595,6650 12575,6630 12355,6630 12325,6660 12325,7070 12350,7095
N179113761 on TOP "TOP-N179113761" (solid, pour order 20): 7000.11,4502.56 7083.62,4502.56 7419.89,4502.56 7435,4487.44 7435,4300 7395,4260 6920,4260 6900,4280 6900,4490 6912.56,4502.56 7000.11,4502.56
N18031698 on TOP "TOP-N18031698" (solid, pour order 21): 20 vertices, not listed, extent 865,4300 1352.5,4585
PGND on TOP "TOP-PGND 1" (solid, pour order 24): 13605,6810 14075,6810 14105,6840 14105,6965 14095,6975 13875,6975 13760,7090 13460,7090 13425,7055 13425,6990 13605,6810
N17916039 on TOP "TOP-N17916039 2" (solid, pour order 26): 19 vertices, not listed, extent 12450,4765 13280.68,5065
N17916039 on TOP "TOP-N17916039" (solid, pour order 29): 18 vertices, not listed, extent 12440,2845 13290,3165
LC on TOP "TOP-LC" (solid, pour order 30): 37 vertices, not listed, extent 250,810 789.21,1342.5
LA on TOP "TOP-LA" (solid, pour order 34): 24 vertices, not listed, extent 250,2210 791.25,2742.5
PGND on TOP "TOP-PGND" (solid, pour order 35): 19 vertices, not listed, extent 12450,4050 13284.68,4600
PGND on TOP "TOP-PGND 4" (solid, pour order 37): 21 vertices, not listed, extent 12450,2115 13284.68,2675
LB on TOP "TOP-LB" (solid, pour order 39): 66 vertices, not listed, extent 250,1510 807.5,2042.5
GND_EARTH on TOP "TOP-GND_EARTH" (solid, pour order 43): 17 vertices, not listed, extent 115,200 947.5,630
AC_LB1 on TOP "TOP-AC_LB1" (solid, pour order 48): 23 vertices, not listed, extent 7695,4075 9085,4505
N17916039 on TOP "TOP-N17916039 1" (solid, pour order 50): 12760,1240 13315,1240 13460,1095 13460,790 13370,700 12755,700 12705,750 12705,1185 12760,1240
N18158495 on TOP "TOP-N18158495" (solid, pour order 51): 50,6515 50,7255.3 75,7280.3 520,7280.3 555,7245.3 555,6470 95,6470 50,6515
N18031715 on TOP "TOP-N18031715" (solid, pour order 60): 23 vertices, not listed, extent 340,4300 835,5190
PGND on TOP "TOP-PGND 2" (solid, pour order 1): 33 vertices, not listed, extent 10010,445 12300,1077.5
N18060364 on TOP "TOP-N18060364" (solid, pour order 65): 355,6335 355,5360 365,5350 955,5350 1125,5180 1300,5180 1340,5220 1340,6300 1295,6345 365,6345 355,6335
AC_LC on TOP "TOP-AC_LC" (solid, pour order 68): 57 vertices, not listed, extent 5475,2570.04 8365,2990
AC_LB on TOP "TOP-AC_LB" (solid, pour order 76): 60 vertices, not listed, extent 5765,2985 8365,4500
N17908062 on TOP "TOP-N17908062" (solid, pour order 77): 74 vertices, not listed, extent 2480,2155 4815,3710
AC_LA on TOP "TOP-AC_LA" (solid, pour order 80): 115 vertices, not listed, extent 4910,1368.75 8377.5,3300
VPFC on TOP "TOP-VPFC" (solid, pour order 94): 69 vertices, not listed, extent 1800,4300 9270,5225
N17920487 on TOP "TOP-N17920487" (solid, pour order 95): 1975,5720 1975,6400 2000,6425 7985,6425 8185,6425 8190,6420 8635,5975 8635,5450 8585,5400 8110,5400 2295,5400 1975,5720
PGND on TOP "TOP-PGND 3" (solid, pour order 98): 31 vertices, not listed, extent 1565,5170 13295,7280.3
GND_EARTH on BOTTOM "BOTTOM-GND_EARTH" (solid, pour order 0): 3355,2635 3355,2755 3335,2775 3280,2775 3270,2775 3265,2770 3265,2630 3270,2625 3280,2625 3345,2625 3355,2635
PGND on BOTTOM "BOTTOM-PGND 1" (solid, pour order 13): 10525,250 10500,275 10500,600 10520,620 10705,620 10725,600 10725,430 10685,390 10640,345 10625,330 10625,265 10610,250 10525,250
AC_LB1 on BOTTOM "BOTTOM-AC_LB1" (solid, pour order 15): 23 vertices, not listed, extent 8870,3960 9280,4285
AC_LA1 on BOTTOM "BOTTOM-AC_LA1" (solid, pour order 16): 24 vertices, not listed, extent 8875,1350 9280,1682.5
AC_LC1 on BOTTOM "BOTTOM-AC_LC1" (solid, pour order 17): 26 vertices, not listed, extent 8860,2665 9280,3005
P6.5V on BOTTOM "BOTTOM-P6.5V" (solid, pour order 22): 18 vertices, not listed, extent 10320,145 11705,805
N17908062 on BOTTOM "BOTTOM-N17908062" (solid, pour order 23): 21 vertices, not listed, extent 2697.3,2065 3085,2655
N17908020 on BOTTOM "BOTTOM-N17908020" (solid, pour order 25): 3385,3600 3635,3600 3665,3630 3665,4190 3650,4205 3380,4205 3347.5,4172.5 3350,4170 3350,3635 3385,3600
N17908062 on BOTTOM "BOTTOM-N17908062 1" (solid, pour order 27): 4815,3495 4690,3370 4200,3370 4125,3445 4125,3690 4167.5,3732.5 4765,3732.5 4815,3682.5 4815,3495
LB on BOTTOM "BOTTOM-LB" (solid, pour order 31): 45 vertices, not listed, extent 260,1510 807.5,2042.5
LC on BOTTOM "BOTTOM-LC" (solid, pour order 32): 46 vertices, not listed, extent 260,810 807.5,1342.5
LA on BOTTOM "BOTTOM-LA" (solid, pour order 33): 47 vertices, not listed, extent 260,2210 807.5,2742.5
N17908018 on BOTTOM "BOTTOM-N17908018" (solid, pour order 36): 20 vertices, not listed, extent 3282.5,2107.5 3795,2760
AGND on BOTTOM "BOTTOM-AGND" (solid, pour order 41): 20 vertices, not listed, extent 9655,780 10710,1155
AC_LC on BOTTOM "BOTTOM-AC_LC" (solid, pour order 42): 7295,2730 7860,2730 8120,2730 8170,2680 8310,2680 8355,2725 8355,2965 8315,3005 7855,3005 7295,3005 7160,3005 7130,2975 7130,2780 7180,2730 7295,2730
N17908016 on BOTTOM "BOTTOM-N17908016" (solid, pour order 44): 2975,1925 3470,1925 3670,1725 3670,1320 3655,1305 3455,1305 3250,1510 3180,1510 2955,1510 2940,1525 2940,1890 2975,1925
AC_LB on BOTTOM "BOTTOM-AC_LB" (solid, pour order 45): 36 vertices, not listed, extent 7127.5,3830 8345,4175
VP+5V on BOTTOM "BOTTOM-VP+5V" (solid, pour order 46): 76 vertices, not listed, extent 9660,90 10200,810
AC_LA on BOTTOM "BOTTOM-AC_LA" (solid, pour order 47): 19 vertices, not listed, extent 7125,1375 8355,1880
DC_14V_INPUT on BOTTOM "BOTTOM-DC_14V_INPUT" (solid, pour order 49): 29 vertices, not listed, extent 12035,150 13290,475
N17916243 on BOTTOM "BOTTOM-N17916243" (solid, pour order 54): 70 vertices, not listed, extent 11785,3230 13285.68,4180
N17916108 on BOTTOM "BOTTOM-N17916108" (solid, pour order 55): 58 vertices, not listed, extent 11782.5,5175 13310.68,6110
N17898200 on BOTTOM "BOTTOM-N17898200" (solid, pour order 56): 91 vertices, not listed, extent 840,2110 2305,2915
N17916066 on BOTTOM "BOTTOM-N17916066" (solid, pour order 57): 60 vertices, not listed, extent 11782.5,1245 13305.68,2265
GND_EARTH on BOTTOM "BOTTOM-GND_EARTH 1" (solid, pour order 58): 54 vertices, not listed, extent 50,50 1140,2550
VPFC on BOTTOM "BOTTOM-VPFC" (solid, pour order 61): 18 vertices, not listed, extent 1840,4315 3035,5165
N18060364 on BOTTOM "BOTTOM-N18060364" (solid, pour order 66): 355,6335 355,5360 365,5350 955,5350 1125,5180 1300,5180 1340,5220 1340,6300 1295,6345 365,6345 355,6335
N17896948 on BOTTOM "BOTTOM-N17896948" (solid, pour order 67): 44 vertices, not listed, extent 1525,1127.5 2677.66,3500
N17896613 on BOTTOM "BOTTOM-N17896613" (solid, pour order 69): 134 vertices, not listed, extent 850,200 3275,1875
AC_LAP on BOTTOM "BOTTOM-AC_LAP" (solid, pour order 71): 22 vertices, not listed, extent 9310,1350 11220,2965
AC_LCP on BOTTOM "BOTTOM-AC_LCP" (solid, pour order 82): 26 vertices, not listed, extent 9310,2665 11325,4965
AC_LBP on BOTTOM "BOTTOM-AC_LBP" (solid, pour order 87): 31 vertices, not listed, extent 9310,3970 11302.5,7000
PGND on BOTTOM "BOTTOM-PGND" (solid, pour order 91): 43 vertices, not listed, extent 1565,5175 7835,7280.3
N17920487 on BOTTOM "BOTTOM-N17920487" (solid, pour order 93): 71 vertices, not listed, extent 1955,5350 8670,6475
VPFC on POWER03 "NONET_L-01_P-001" (solid, pour order 103): 1850,4300 1800,4350 1800,4695 2095,4990 2095,5825 2225,5955 9135,5955 9260,5830 9260,4685 9200,4625 3375,4625 3050,4300
N18031715 on POWER03 "POWER03-N18031715" (solid, pour order 28): 340,4515 340,5020 355,5035 765,5035 800,5000 800,4935 800,4920 800,4530 765,4495 360,4495 340,4515
IGND on POWER03 "POWER03-IGND" (solid, pour order 40): 12040,170 12025,185 12025,450 12050,475 13075,475 13115,435 13115,210 13075,170 12566.1,170 12566.1,235 12496.1,235 12496.1,170 12040,170
AC_LB1 on POWER03 "POWER03-AC_LB1" (solid, pour order 52): 7760,4510 9040,4510 9095,4455 9095,4145 9020,4070 8805,4070 8660,4215 7765,4215 7725,4255 7725,4475 7760,4510
N18060364 on POWER03 "POWER03-N18060364" (solid, pour order 63): 355,6335 355,5360 365,5350 955,5350 1125,5180 1300,5180 1340,5220 1340,6300 1295,6345 365,6345 355,6335
GGND on POWER03 "POWER03-GGND" (solid, pour order 73): 14361,1006 14335,980 14135,980 14110,1005 14110,6350 14130,6370 14341,6370 14361,6350 14361,1006
AC_LC on POWER03 "POWER03-AC_LC" (solid, pour order 75): 5635,2905 6995,2905 7125,3035 7850,3035 8310,3035 8360,2985 8360,2525 8295,2460 7805,2460 5630,2460 5505,2460 5475,2490 5475,2865 5515,2905 5635,2905
AGND on POWER03 "POWER03-AGND" (solid, pour order 84): 248 vertices, not listed, extent 205,93 3395,4025
N17908020 on POWER03 "POWER03-N17908020" (solid, pour order 85): 31 vertices, not listed, extent 3390,1280 4826.11,4240
AC_LB on POWER03 "POWER03-AC_LB" (solid, pour order 88): 5895,3015 5800,3110 5800,4425 5885,4510 7135,4510 7475,4170 8340,4170 8385,4125 8385,3785 8335,3735 7450,3735 6730,3015 5895,3015
AC_LA on POWER03 "POWER03-AC_LA" (solid, pour order 89): 40 vertices, not listed, extent 5015,1362.5 8360,3250
N17898311 on POWER03 "POWER03-N17898311" (solid, pour order 92): 182 vertices, not listed, extent 825,730 4155,3245
PGND on POWER03 "POWER03-PGND" (solid, pour order 100): 17 vertices, not listed, extent 1565,5170 12230.86,7280.3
